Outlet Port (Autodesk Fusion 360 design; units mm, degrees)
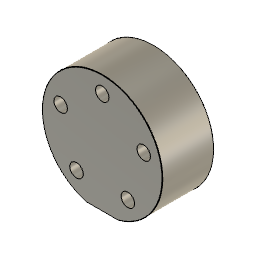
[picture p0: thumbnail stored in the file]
sketch "Sketch1" plane through (0, 0, 0) normal (1, 0, 0) x axis (0, 1, 0)
  line L1 (109.277, 0) -> (0, 0)
  line L2 (0, 6.604) -> (0, 22.225)
  line L3 (19.05, 6.604) -> (0, 6.604)
  line L4 (0, 22.225) -> (19.05, 22.225)
  line L5 (19.05, 11.9507) -> (19.05, 22.225)
  line L6 (17.6784, 11.9507) -> (19.05, 11.9507)
  line L7 (17.6784, 9.3345) -> (17.6784, 11.9507)
  line L8 (19.05, 9.3345) -> (17.6784, 9.3345)
  line L9 (19.05, 6.604) -> (19.05, 9.3345)
  line L10 (0, 0) -> (0, 6.604)
  line L11 (19.05, 0) -> (19.05, 6.604)
  line L12 (19.05, 0) -> (0, 0)
  point P1 (0, 0)
  point P2 (0, 0)
  point P5 (0, 6.604)
  point P8 (19.05, 11.9507)
  point P11 (19.05, 9.3345)
  point P12 (0, 0)
  point P13 (19.05, 0)
  point P14 (0, 0)
  point P4 (0, 22.225)
  point P7 (19.05, 22.225)
  point P9 (17.6784, 11.9507)
  coincident P1 P2
  horizontal L1
  vertical L2
  perpendicular L2 L3
  perpendicular L2 L4
  perpendicular L4 L5
  perpendicular L5 L6
  perpendicular L6 L7
  perpendicular L7 L8
  perpendicular L3 L9
  vertical P1 P5
  vertical P8 P11
  coincident P1 P12
  coincident L1 P13
  perpendicular L1 L11
  coincident P1 P14
  dimension "d1" distance P4 P7 = 19.05
  dimension "d2" distance P1 L4 = 22.225 (= "( 1.75 / 2 ) * 1 in")
  dimension "d3" distance P1 L3 = 6.604 (= "0.25 in + 0.01 in")
  dimension "d4" distance L1 L6 = 11.9507
  dimension "d5" distance L1 L8 = 9.3345
  dimension "d6" distance P8 P9 = 1.3716
revolve "Revolve1" sketch "Sketch1" AlongAngle 360
sketch "Sketch2" plane through (0, 0, 0) normal (0, -1, 0) x axis (1, 0, 0)
  circle C1 centre (0, 16.129) radius 2.4892
  circle C2 centre (0, 0) radius 22.225
  point P1 (0, 0)
  point P2 (0, 16.129)
  vertical P1 P2
  dimension "d10" diameter C1 = 4.9784
  dimension "d24" distance P1 P2 = 16.129
extrude "Extrude1" cut sketch "Sketch2" profile of C1 to an object
circular_pattern "C-Pattern1" TotalAngle 360
work_plane "WorkPlane1" RotateAngle 90
sketch "Sketch3" plane through (0, 0, 0) normal (0, -1, 0) x axis (1, 0, 0)
  circle C1 centre (-15.3396, 4.9841) radius 2.4892
  circle C2 centre (-9.4804, -13.0486) radius 2.4892
  circle C3 centre (9.4804, -13.0486) radius 2.4892
  circle C4 centre (15.3396, 4.9841) radius 2.4892
  circle C5 centre (0, 16.129) radius 2.4892
  circle C6 centre (0, 0) radius 22.225
hole "Hole2" HoleDepth 15.621 HoleDiameter 13.716 TipAngle 180
chamfer "Chamfer3" distance 0.127
chamfer "Chamfer4" distance 0.127
sketch "Sketch7" plane through (0, 0, -22.225) normal (0, 0, -1) x axis (-1, 0, 0)
  line L1 (6.985, 15.875) -> (-6.985, 15.875)
  line L2 (6.985, 1.905) -> (6.985, 15.875)
  line L3 (-6.985, 1.905) -> (6.985, 1.905)
  line L4 (-6.985, 15.875) -> (-6.985, 1.905)
  line L5 (0, 4.9156) -> (0, 1.905)
  line L6 (-1.263, 8.89) -> (6.985, 8.89)
  line L7 (0, 19.05) -> (0, 0)
  point P6 (0, 1.905)
  point P8 (6.985, 8.89)
  point P1 (0, 0)
  point P10 (0, 0)
  point P7 (0, 4.9156)
  point P2 (-6.985, 15.875)
  point P3 (6.985, 15.875)
  horizontal L1
  vertical L2
  horizontal L3
  vertical L4
  equal L1 L2
  midpoint L3 P6
  perpendicular L3 L5
  midpoint L2 P8
  perpendicular L2 L6
  coincident P1 P10
  vertical L7
  coincident P7 L7
  dimension "d33" distance P2 P3 = 13.97
  dimension "d34" distance P1 L6 = 8.89
extrude "Extrude2" add sketch "Sketch7" profile of L1 L2 L3 L4 against normal blind 2.54
sketch "Sketch8" plane through (0, 0, -22.225) normal (0, 0, -1) x axis (1, 0, 0)
  line L1 (6.985, -15.875) -> (0, -15.875)
  line L2 (6.985, -1.905) -> (6.985, -15.875)
  line L3 (0, -1.905) -> (6.985, -1.905)
  line L4 (-6.985, -1.905) -> (0, -1.905)
  line L5 (-6.985, -15.875) -> (-6.985, -1.905)
  line L6 (0, -15.875) -> (-6.985, -15.875)
  line L7 (0, -19.05) -> (0, 0)
  line L8 (-22.098, -19.05) -> (22.098, -19.05)
  line L9 (22.098, 0) -> (-22.098, 0)
  line L10 (22.098, 0) -> (-22.098, 0)
  line L11 (22.098, -19.05) -> (22.098, 0)
  line L12 (-22.098, -19.05) -> (22.098, -19.05)
  line L13 (-22.098, 0) -> (-22.098, -19.05)
  circle C1 centre (0, -8.89) radius 1.27
  point P1 (0, 0)
  point P9 (0, 0)
  point P10 (0, -19.05)
  point P8 (0, -8.89)
  point P11 (22.098, -19.05)
  point P17 (22.098, -19.05)
  point P13 (-22.098, 0)
  point P15 (-22.098, 0)
  coincident P1 P9
  perpendicular L6 L7
  coincident P10 L8
  coincident P8 L7
  horizontal L10
  vertical L11
  horizontal L12
  vertical L13
  coincident P11 P17
  coincident P13 P15
  dimension "d37" diameter C1 = 2.54
  dimension "d43" distance P8 L9 = 8.89
hole "Hole3" HoleDepth 20.32 HoleDiameter 10.7188 TipAngle 118
extrude "Extrude3" cut sketch "Sketch8" profile of L1 L2 L3 L4 L5 L6 C1 L10 L11 L12 L13 against normal blind 0.889
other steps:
thread "Thread2" ThreadOffset 0 ThreadDepth 0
